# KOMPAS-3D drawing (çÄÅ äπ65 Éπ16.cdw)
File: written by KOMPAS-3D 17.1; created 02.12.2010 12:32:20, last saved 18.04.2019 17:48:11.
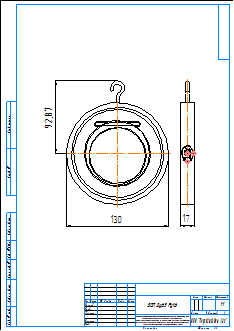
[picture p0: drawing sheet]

Sheet 1: A3, portrait

Title block, sheet 1: name: ЗОП Ду65 Ру16; material: Внимание! Данный продукт является объектом авторского права ООО «Торговый Дом АДЛ». / Запрещается изменение, копирование, распространение / (в том числе путем копирования на другие сайты и ресурсы в Интернете) / или любое иное использование информации и объектов без предварительного / согласия правообладателя (ООО «Торговый Дом АДЛ»).; scale: 1:1; sheets: 1; organisation: ООО "Торговый дом АДЛ"; sheet format: A3; stored path: \\adlc.lan\data\АДЛ_ПКД\3D-модели\ADL production\Клапаны обратные ГРАНЛОК\ЗОП\KOMPAS 2D\ЗОП Ду65 Ру16.cdw

Views: Спереди 1, Проекционный вид 2
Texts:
  bsv
  adl
Dimensions and other numbers on the sheet: 130; 17; 92,87; 1:1; 1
